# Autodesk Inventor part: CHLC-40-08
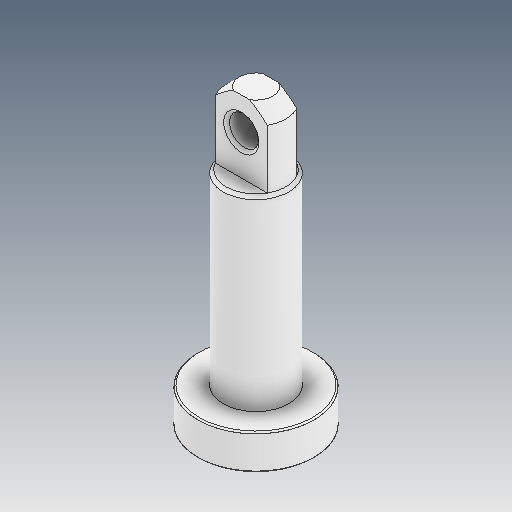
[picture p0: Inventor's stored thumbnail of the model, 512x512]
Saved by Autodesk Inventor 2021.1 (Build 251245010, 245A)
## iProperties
Created: 2021-05
Part Number: CHLC-40-08
Material: Ogólny
Document SubType Name: Modeling
Designer: user
Density: 1 g/cm^3
Appearance: Domyślna
Author: user
Revision Number: ÈÎºÎ
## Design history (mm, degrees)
feature "µ¹½Ç2"
node "Bryła1"
